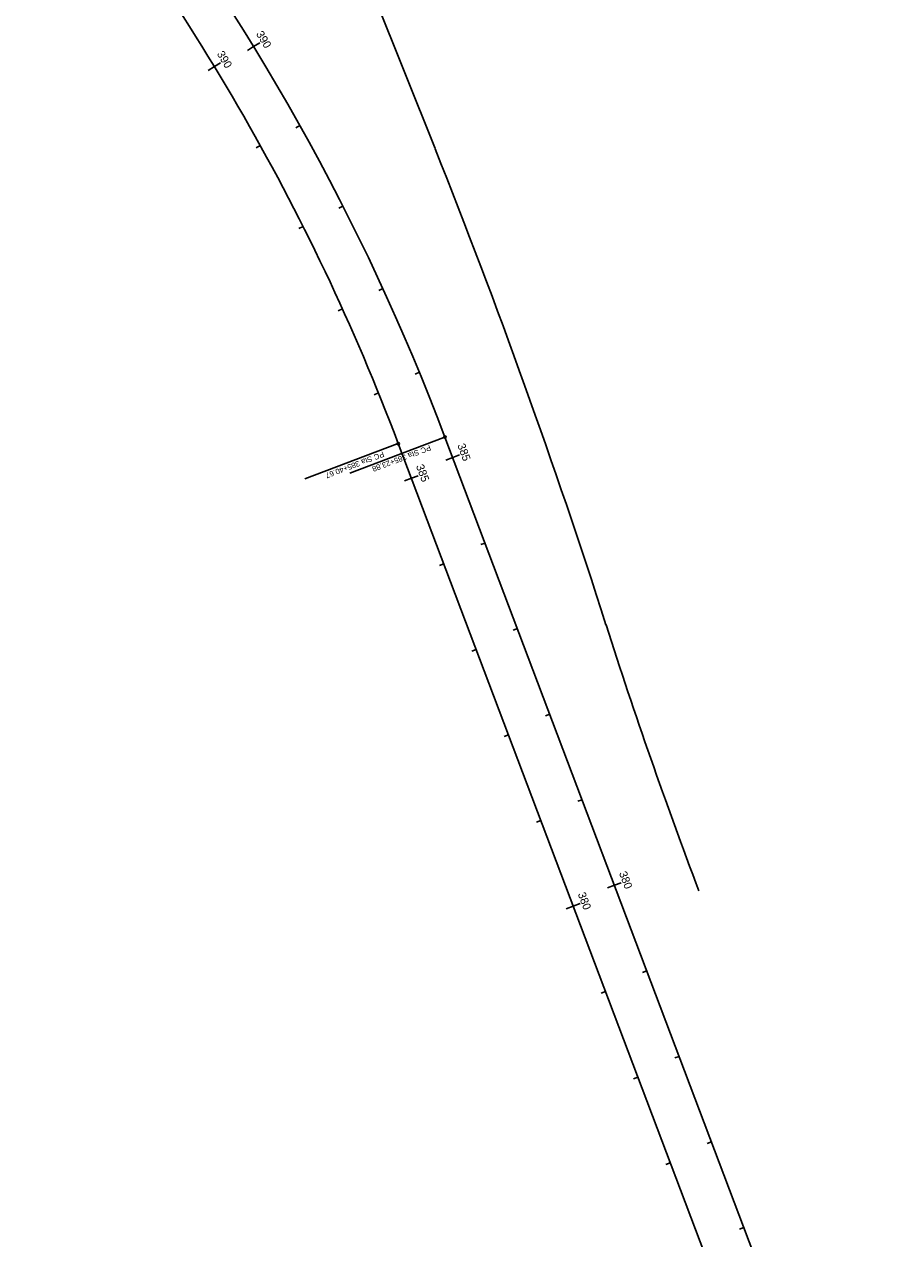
# Model space of a CAD drawing. Extents: x 1602163 to 1612907, y 1087635 to 1096265.
# Drawn here: x 1611133 to 1612071, y 1091937 to 1093265 of the extents above; entities that cross this region are included whole.
import ezdxf

# ---------------------------------------------------------------- set-up
doc = ezdxf.new("R2010")
doc.units = 0
for name, color, linetype in [('RD_HC_Cl', 7, 'Continuous'), ('RD_HC_CL_200', 7, 'Continuous'), ('RD_HC_Data_Tic', 7, 'Continuous'), ('RD_HC_Points', 7, 'Continuous'), ('RD_HC_TX_Sta50', 7, 'Continuous')]:
    doc.layers.add(name, color=color, linetype=linetype)

msp = doc.modelspace()

# ---------------------------------------------------------------- linework, layer by layer
at = {"layer": 'RD_HC_Cl'}
for p, q in [((1612071.1, 1091550.5), (1611593.4, 1092813.6)), ((1611906.2, 1091844.6), (1611542.3, 1092806.5))]:
    msp.add_line(p, q, dxfattribs=at)
for centre, radius, end in [((1609225.7, 1091930.4), 2476.8, 39.6334), ((1609233.5, 1091921.1), 2523, 37.9336)]:
    msp.add_arc(centre, radius, 20.7167, end, dxfattribs=at)
at = {"layer": 'RD_HC_CL_200'}
msp.add_line((1611582.6, 1093128.9), (1611474, 1093401.3), dxfattribs=at)
for centre, radius, start, end in [((1604151.3, 1090166.4), 8000, 17.77323, 21.73435), ((1617483.2, 1094439.9), 6000, 197.77323, 200.71665)]:
    msp.add_arc(centre, radius, start, end, dxfattribs=at)
at = {"layer": 'RD_HC_Data_Tic'}
for p, q in [((1611384.1, 1093240.4), (1611377.3, 1093236.3)), ((1611384.1, 1093240.4), (1611390.9, 1093244.6)), ((1611341.1, 1093218.7), (1611347.9, 1093222.8)), ((1611341.1, 1093218.7), (1611334.2, 1093214.5)), ((1611434.7, 1093154.2), (1611430.3, 1093151.8)), ((1611391.3, 1093132.3), (1611387, 1093129.8)), ((1611481.8, 1093066), (1611477.3, 1093063.7)), ((1611438.1, 1093043.9), (1611433.6, 1093041.6)), ((1611525.4, 1092976), (1611520.9, 1092973.9)), ((1611481.2, 1092953.7), (1611476.7, 1092951.6)), ((1611565.4, 1092884.4), (1611560.8, 1092882.5)), ((1611520.7, 1092861.8), (1611516.1, 1092859.9)), ((1611601.8, 1092791.3), (1611594.4, 1092788.4)), ((1611601.8, 1092791.3), (1611609.3, 1092794.1)), ((1611556.7, 1092768.5), (1611564.2, 1092771.3)), ((1611556.7, 1092768.5), (1611549.2, 1092765.7)), ((1611637.2, 1092697.7), (1611632.5, 1092696)), ((1611592.1, 1092675), (1611587.4, 1092673.2)), ((1611672.6, 1092604.2), (1611667.9, 1092602.4)), ((1611627.5, 1092581.4), (1611622.8, 1092579.7)), ((1611708, 1092510.7), (1611703.3, 1092508.9)), ((1611662.9, 1092487.9), (1611658.2, 1092486.1)), ((1611743.3, 1092417.1), (1611738.7, 1092415.4)), ((1611698.2, 1092394.4), (1611693.6, 1092392.6)), ((1611778.7, 1092323.6), (1611771.2, 1092320.8)), ((1611778.7, 1092323.6), (1611786.2, 1092326.4)), ((1611733.6, 1092300.8), (1611726.1, 1092298)), ((1611733.6, 1092300.8), (1611741.1, 1092303.7)), ((1611814.1, 1092230.1), (1611809.4, 1092228.3)), ((1611769, 1092207.3), (1611764.3, 1092205.5)), ((1611849.5, 1092136.5), (1611844.8, 1092134.8)), ((1611804.4, 1092113.8), (1611799.7, 1092112)), ((1611884.8, 1092043), (1611880.2, 1092041.2)), ((1611839.7, 1092020.2), (1611835.1, 1092018.5)), ((1611920.2, 1091949.5), (1611915.5, 1091947.7))]:
    msp.add_line(p, q, dxfattribs=at)
at = {"layer": 'RD_HC_Points'}
for p, q in [((1611592.2, 1092813.2), (1611489.3, 1092774.2)), ((1611541.2, 1092806.1), (1611440.2, 1092767.9))]:
    msp.add_line(p, q, dxfattribs=at)
for centre in [(1611593.4, 1092813.6), (1611542.3, 1092806.5)]:
    msp.add_circle(centre, 1.25, dxfattribs=at)

# ---------------------------------------------------------------- texts
for s, p in [('PC Sta 385+40.67', (1611525.5, 1092798)), ('PC Sta 385+23.88', (1611576.6, 1092805.1))]:
    msp.add_text(s, height=6, rotation=200.7167, dxfattribs=at).set_placement(p)
at = {"layer": 'RD_HC_TX_Sta50'}
for s, rotation, p in [('390', 301.5291, (1611386.4, 1093254.3)), ('390', 301.3426, (1611343.5, 1093232.5)), ('385', 290.7167, (1611606.7, 1092804.7)), ('385', 290.7167, (1611561.5, 1092781.9)), ('380', 290.7167, (1611783.6, 1092336.9)), ('380', 290.7167, (1611738.5, 1092314.1))]:
    msp.add_text(s, height=8.75, rotation=rotation, dxfattribs=at).set_placement(p)

doc.saveas('drawing.dxf')
